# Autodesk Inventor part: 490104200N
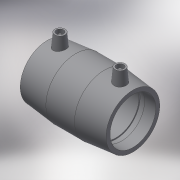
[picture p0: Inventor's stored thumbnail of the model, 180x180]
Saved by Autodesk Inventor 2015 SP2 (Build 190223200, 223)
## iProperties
Created: 2017-06
Part Number: 490104200N
Material: Generic
Description: PLASSON COUPLER 200-200
Document SubType Name: Modeling
Designer: KIM
Mass: 2662.71 g
Surface Area: 3360.78 cm^2
Volume: 2662.71 cm^3
Density: 1 g/cm^3
Appearance: Default
Author: KIM
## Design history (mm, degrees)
derived "490104.ipt"
feature "Solid1::490104.ipt"
tag "TaggingFeature1"
body "Solid1"
other parameters: "d0" = 223, "d2" = 242, "d3" = 109, "d4" = 74.33333, "d5" = 217.8, "d8" = 168 deg, "d10" = 43.6, "d11" = 14.53333, "d13" = 223, "d14" = 17.6296, "d15" = 109, "d16" = 109, "d19" = 3.52592, "d20" = 168 deg, "d22" = 227.48, "d23" = 242, "d24" = 220.6556, "d25" = 135 deg, "d26" = 111.5, "d27" = 135 deg, "d29" = 126, "d30" = 14, "d31" = 78.05, "d34" = 5 deg, "d35" = 15, "d39" = 5 deg, "d41" = 4, "d42" = 14, "d43" = 0, "d45" = 4, "d46" = 14, "d47" = 0, "d48" = 3, "d49" = 0, "d50" = 3, "d51" = 0, "d52" = 31.61, "d53" = 7.9025, "L_" = 223, "L_1" = 109, "D_" = 242, "A_" = 126, "d_2" = 12
